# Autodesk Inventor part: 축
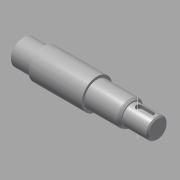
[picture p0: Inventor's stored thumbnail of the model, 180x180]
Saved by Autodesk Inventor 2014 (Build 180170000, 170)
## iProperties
Created: 2016-06
Part Number: 축
Material: 강철, 연강
Document SubType Name: Modeling
Designer: mduedu
Density: 7.86 g/cm^3
Appearance: Steel
Author: mduedu
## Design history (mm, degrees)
sketch "스케치1"
  geometry: L1 (-53.5, 0)-(53.5, 0); L2 (-53.5, 0)-(-53.5, 10); L3 (-53.5, 10)-(-36.5, 10); L4 (-36.5, 10)-(-36.5, 12); L5 (-36.5, 12)-(5.5, 12); L6 (5.5, 12)-(5.5, 10); L7 (5.5, 10)-(33.5, 10); L8 (33.5, 10)-(33.5, 8); L9 (33.5, 8)-(53.5, 8); L10 (53.5, 8)-(53.5, 0); 2 further points
  constraints: 20 end point, 5 parallel, 2 perpendicular, 1 coincident, 1 collinear, 1 horizontal, 1 midpoint, 1 vertical
  dimensions: "d0" = 107 distance of L1.start L1.end; "d2" = 16 diameter of L9 L1; "d3" = 20 diameter of L7 L1; "d4" = 24 diameter of L5 L1; "d5" = 20 diameter of L3 L1; "d6" = 17 distance of L2.end L3.end; "d7" = 20 distance of L8.end L9.end; "d8" = 48 distance from line of L5.end L10
revolve "회전1" sketch "스케치1" stored, may be unused: angle "d9" = 90 deg
chamfer "모따기1" distance "d10" = 2; stored, may be unused: second distance "d11" = 2, angle "d12" = 30 deg
fillet "모깎기1" dims "d13" = 2
node "작업 평면1"
sketch "스케치2"
  geometry: L1 (-4.5, 2.5)-(4.5, 2.5); L2 (4.5, -2.5)-(-4.5, -2.5); L3 (-4.5, 0)-(4.5, 0); L4 (-10, 8.845)-(-10, -8.845) reference; A1 r 2.5 centre (-4.5, 0) between (-4.5, 2.5) and (-4.5, -2.5); A2 r 2.5 centre (4.5, 0) between (4.5, -2.5) and (4.5, 2.5); 1 further point
  constraints: 6 end point, 4 point on circle, 3 tangent, 2 centre point, 2 parallel, 1 horizontal, 1 horizontal alignment
  dimensions: "d14" = 3 distance edge to line of A1 L4; "d15" = 5 distance between parallel lines of L2 L1; "d16" = 14 dimension on A2 A1
extrude "돌출1" cut sketch "스케치2" distance "d17" = 3; taper "d18" = 0 deg
chamfer "모따기2" distance "d19" = 1; stored, may be unused: second distance "d20" = 2, angle "d21" = 30 deg
sketch "스케치3"
  geometry: L1 (-33.5, -8)-(-52.5, -8) reference; L2 (-53.5, -7)-(-53.5, 7) reference; L3 (-36, -8)-(-37.5, -6.5); L4 (-37.5, -6.5)-(-37.5, -8); L5 (-36, -8)-(-37.5, -8); 1 further point
  constraints: 6 end point, 2 point on line, 1 collinear, 1 vertical
  dimensions: "d22" = 45 deg angle of L4 L3; "d23" = 16 distance between parallel lines of L2 L4; "d24" = 3 diameter of L3.start L4
revolve "회전2" stored, may be unused: angle "d25" = 90 deg
node "작업점1"
sketch "스케치4"
  geometry: 1 further point
hole "구멍1" sketch "스케치4" at (0, 0) diameter "d26" = 3.242; stored, may be unused: countersink angle "d30" = 90 deg, drill point angle "d32" = 120 deg; dims "d27" = 8, "d28" = 4, "d29" = 2, "d31" = 11
chamfer "모따기3" distance "d33" = 2; stored, may be unused: second distance "d34" = 2, angle "d35" = 30 deg
workpoint "Work Point2"
  workaxis "Work Axis1"
node "솔리드1"
